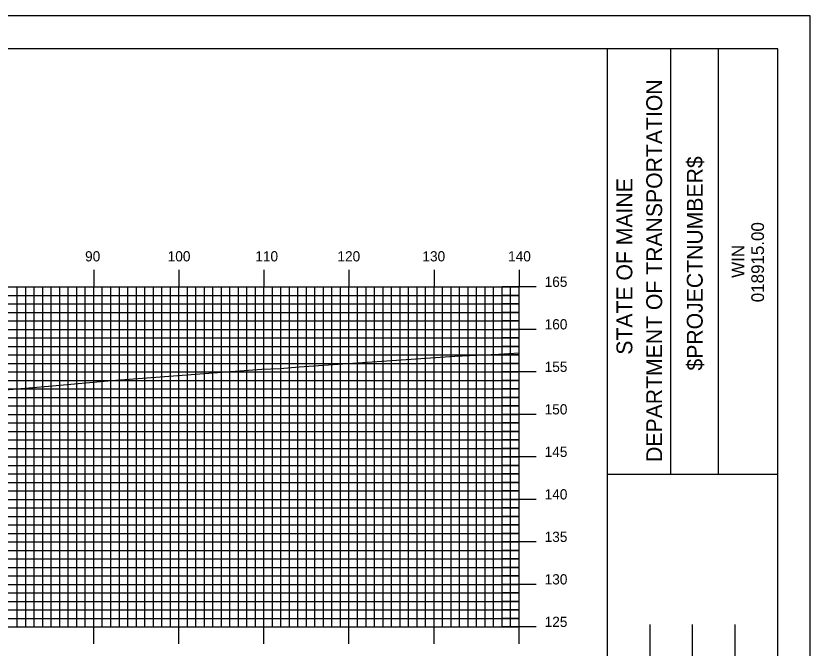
# Model space of a CAD drawing. Extents: x 1782647 to 1782990, y 442591 to 442811.
# Drawn here: x 1782893.8 to 1782987.2, y 442736.2 to 442810.5 of the extents above; entities that cross this region are included whole.
import ezdxf

# ---------------------------------------------------------------- set-up
doc = ezdxf.new("R2010")
doc.units = 0
for name, color, linetype in [('BORDER', 7, 'Continuous'), ('H_V ANNOTATION', 7, 'Continuous'), ('MAJOR', 7, 'Continuous'), ('MINOR', 7, 'Continuous'), ('PLOT BOUNDARY', 7, 'Continuous'), ('S_Roadway_Centerline', 7, 'Continuous')]:
    doc.layers.add(name, color=color, linetype=linetype)

msp = doc.modelspace()

# ---------------------------------------------------------------- linework, layer by layer
at = {"layer": 'BORDER'}
for p, q in [((1782963.347, 442596.665), (1782963.347, 442806.665)), ((1782970.804, 442756.659), (1782970.804, 442806.659)), ((1782976.394, 442756.659), (1782976.394, 442806.659)), ((1782963.349, 442756.653), (1782983.347, 442756.653)), ((1782963.349, 442756.653), (1782983.347, 442756.653)), ((1782968.347, 442721.671), (1782968.347, 442738.966)), ((1782968.347, 442721.671), (1782968.347, 442738.966)), ((1782973.347, 442721.671), (1782973.347, 442738.966)), ((1782973.347, 442721.671), (1782973.347, 442738.966)), ((1782978.347, 442721.671), (1782978.347, 442738.966)), ((1782978.347, 442721.671), (1782978.347, 442738.966))]:
    msp.add_line(p, q, dxfattribs=at)
msp.add_lwpolyline([(1782663.347, 442596.665), (1782983.347, 442596.665), (1782983.347, 442806.665), (1782663.347, 442806.665)], close=True, dxfattribs=at)
at = {"layer": 'MAJOR'}
for p, q in [((1782902.947, 442780.669), (1782902.947, 442778.665)), ((1782912.947, 442780.669), (1782912.947, 442778.665)), ((1782922.947, 442780.669), (1782922.947, 442778.665)), ((1782932.947, 442780.669), (1782932.947, 442778.665)), ((1782942.947, 442780.669), (1782942.947, 442778.665)), ((1782952.947, 442780.669), (1782952.947, 442778.665)), ((1782672.947, 442778.665), (1782952.947, 442778.665)), ((1782672.947, 442778.665), (1782952.947, 442778.665)), ((1782902.947, 442738.665), (1782902.947, 442778.665)), ((1782912.947, 442738.665), (1782912.947, 442778.665)), ((1782922.947, 442738.665), (1782922.947, 442778.665)), ((1782932.947, 442738.665), (1782932.947, 442778.665)), ((1782942.947, 442738.665), (1782942.947, 442778.665)), ((1782954.951, 442778.665), (1782950.943, 442778.665)), ((1782952.947, 442738.665), (1782952.947, 442778.665)), ((1782952.947, 442738.665), (1782952.947, 442778.665)), ((1782672.947, 442773.665), (1782952.947, 442773.665)), ((1782954.951, 442773.665), (1782950.943, 442773.665)), ((1782672.947, 442768.665), (1782952.947, 442768.665)), ((1782954.951, 442768.665), (1782950.943, 442768.665)), ((1782672.947, 442763.665), (1782952.947, 442763.665)), ((1782954.951, 442763.665), (1782950.943, 442763.665)), ((1782672.947, 442758.665), (1782952.947, 442758.665)), ((1782954.951, 442758.665), (1782950.943, 442758.665)), ((1782672.947, 442753.665), (1782952.947, 442753.665)), ((1782954.951, 442753.665), (1782950.943, 442753.665)), ((1782672.947, 442748.665), (1782952.947, 442748.665)), ((1782954.951, 442748.665), (1782950.943, 442748.665)), ((1782672.947, 442743.665), (1782952.947, 442743.665)), ((1782954.951, 442743.665), (1782950.943, 442743.665)), ((1782672.947, 442738.665), (1782952.947, 442738.665)), ((1782672.947, 442738.665), (1782952.947, 442738.665)), ((1782902.947, 442736.661), (1782902.947, 442738.665)), ((1782912.947, 442736.661), (1782912.947, 442738.665)), ((1782922.947, 442736.661), (1782922.947, 442738.665)), ((1782932.947, 442736.661), (1782932.947, 442738.665)), ((1782942.947, 442736.661), (1782942.947, 442738.665)), ((1782954.951, 442738.665), (1782950.943, 442738.665)), ((1782952.947, 442736.661), (1782952.947, 442738.665))]:
    msp.add_line(p, q, dxfattribs=at)
at = {"layer": 'MINOR'}
for p, q in [((1782893.947, 442738.665), (1782893.947, 442778.665)), ((1782894.947, 442738.665), (1782894.947, 442778.665)), ((1782895.947, 442738.665), (1782895.947, 442778.665)), ((1782896.947, 442738.665), (1782896.947, 442778.665)), ((1782897.947, 442738.665), (1782897.947, 442778.665)), ((1782898.947, 442738.665), (1782898.947, 442778.665)), ((1782899.947, 442738.665), (1782899.947, 442778.665)), ((1782900.947, 442738.665), (1782900.947, 442778.665)), ((1782901.947, 442738.665), (1782901.947, 442778.665)), ((1782903.947, 442738.665), (1782903.947, 442778.665)), ((1782904.947, 442738.665), (1782904.947, 442778.665)), ((1782905.947, 442738.665), (1782905.947, 442778.665)), ((1782906.947, 442738.665), (1782906.947, 442778.665)), ((1782907.947, 442738.665), (1782907.947, 442778.665)), ((1782908.947, 442738.665), (1782908.947, 442778.665)), ((1782909.947, 442738.665), (1782909.947, 442778.665)), ((1782910.947, 442738.665), (1782910.947, 442778.665)), ((1782911.947, 442738.665), (1782911.947, 442778.665)), ((1782913.947, 442738.665), (1782913.947, 442778.665)), ((1782914.947, 442738.665), (1782914.947, 442778.665)), ((1782915.947, 442738.665), (1782915.947, 442778.665)), ((1782916.947, 442738.665), (1782916.947, 442778.665)), ((1782917.947, 442738.665), (1782917.947, 442778.665)), ((1782918.947, 442738.665), (1782918.947, 442778.665)), ((1782919.947, 442738.665), (1782919.947, 442778.665)), ((1782920.947, 442738.665), (1782920.947, 442778.665)), ((1782921.947, 442738.665), (1782921.947, 442778.665)), ((1782923.947, 442738.665), (1782923.947, 442778.665)), ((1782924.947, 442738.665), (1782924.947, 442778.665)), ((1782925.947, 442738.665), (1782925.947, 442778.665)), ((1782926.947, 442738.665), (1782926.947, 442778.665)), ((1782927.947, 442738.665), (1782927.947, 442778.665)), ((1782928.947, 442738.665), (1782928.947, 442778.665)), ((1782929.947, 442738.665), (1782929.947, 442778.665)), ((1782930.947, 442738.665), (1782930.947, 442778.665)), ((1782931.947, 442738.665), (1782931.947, 442778.665)), ((1782933.947, 442738.665), (1782933.947, 442778.665)), ((1782934.947, 442738.665), (1782934.947, 442778.665)), ((1782935.947, 442738.665), (1782935.947, 442778.665)), ((1782936.947, 442738.665), (1782936.947, 442778.665)), ((1782937.947, 442738.665), (1782937.947, 442778.665)), ((1782938.947, 442738.665), (1782938.947, 442778.665)), ((1782939.947, 442738.665), (1782939.947, 442778.665)), ((1782940.947, 442738.665), (1782940.947, 442778.665)), ((1782941.947, 442738.665), (1782941.947, 442778.665)), ((1782943.947, 442738.665), (1782943.947, 442778.665)), ((1782944.947, 442738.665), (1782944.947, 442778.665)), ((1782945.947, 442738.665), (1782945.947, 442778.665)), ((1782946.947, 442738.665), (1782946.947, 442778.665)), ((1782947.947, 442738.665), (1782947.947, 442778.665)), ((1782948.947, 442738.665), (1782948.947, 442778.665)), ((1782949.947, 442738.665), (1782949.947, 442778.665)), ((1782950.947, 442738.665), (1782950.947, 442778.665)), ((1782951.947, 442738.665), (1782951.947, 442778.665)), ((1782672.947, 442777.665), (1782952.947, 442777.665)), ((1782952.947, 442777.665), (1782950.943, 442777.665)), ((1782672.947, 442776.665), (1782952.947, 442776.665)), ((1782952.947, 442776.665), (1782950.943, 442776.665)), ((1782672.947, 442775.665), (1782952.947, 442775.665)), ((1782952.947, 442775.665), (1782950.943, 442775.665)), ((1782672.947, 442774.665), (1782952.947, 442774.665)), ((1782952.947, 442774.665), (1782950.943, 442774.665)), ((1782672.947, 442772.665), (1782952.947, 442772.665)), ((1782952.947, 442772.665), (1782950.943, 442772.665)), ((1782672.947, 442771.665), (1782952.947, 442771.665)), ((1782952.947, 442771.665), (1782950.943, 442771.665)), ((1782672.947, 442770.665), (1782952.947, 442770.665)), ((1782952.947, 442770.665), (1782950.943, 442770.665)), ((1782672.947, 442769.665), (1782952.947, 442769.665)), ((1782952.947, 442769.665), (1782950.943, 442769.665)), ((1782672.947, 442767.665), (1782952.947, 442767.665)), ((1782952.947, 442767.665), (1782950.943, 442767.665)), ((1782672.947, 442766.665), (1782952.947, 442766.665)), ((1782952.947, 442766.665), (1782950.943, 442766.665)), ((1782672.947, 442765.665), (1782952.947, 442765.665)), ((1782952.947, 442765.665), (1782950.943, 442765.665)), ((1782672.947, 442764.665), (1782952.947, 442764.665)), ((1782952.947, 442764.665), (1782950.943, 442764.665)), ((1782672.947, 442762.665), (1782952.947, 442762.665)), ((1782952.947, 442762.665), (1782950.943, 442762.665)), ((1782672.947, 442761.665), (1782952.947, 442761.665)), ((1782952.947, 442761.665), (1782950.943, 442761.665)), ((1782672.947, 442760.665), (1782952.947, 442760.665)), ((1782952.947, 442760.665), (1782950.943, 442760.665)), ((1782672.947, 442759.665), (1782952.947, 442759.665)), ((1782952.947, 442759.665), (1782950.943, 442759.665)), ((1782672.947, 442757.665), (1782952.947, 442757.665)), ((1782952.947, 442757.665), (1782950.943, 442757.665)), ((1782672.947, 442756.665), (1782952.947, 442756.665)), ((1782952.947, 442756.665), (1782950.943, 442756.665)), ((1782672.947, 442755.665), (1782952.947, 442755.665)), ((1782952.947, 442755.665), (1782950.943, 442755.665)), ((1782672.947, 442754.665), (1782952.947, 442754.665)), ((1782952.947, 442754.665), (1782950.943, 442754.665)), ((1782672.947, 442752.665), (1782952.947, 442752.665)), ((1782952.947, 442752.665), (1782950.943, 442752.665)), ((1782672.947, 442751.665), (1782952.947, 442751.665)), ((1782952.947, 442751.665), (1782950.943, 442751.665)), ((1782672.947, 442750.665), (1782952.947, 442750.665)), ((1782952.947, 442750.665), (1782950.943, 442750.665)), ((1782672.947, 442749.665), (1782952.947, 442749.665)), ((1782952.947, 442749.665), (1782950.943, 442749.665)), ((1782672.947, 442747.665), (1782952.947, 442747.665)), ((1782952.947, 442747.665), (1782950.943, 442747.665)), ((1782672.947, 442746.665), (1782952.947, 442746.665)), ((1782952.947, 442746.665), (1782950.943, 442746.665)), ((1782672.947, 442745.665), (1782952.947, 442745.665)), ((1782952.947, 442745.665), (1782950.943, 442745.665)), ((1782672.947, 442744.665), (1782952.947, 442744.665)), ((1782952.947, 442744.665), (1782950.943, 442744.665)), ((1782672.947, 442742.665), (1782952.947, 442742.665)), ((1782952.947, 442742.665), (1782950.943, 442742.665)), ((1782672.947, 442741.665), (1782952.947, 442741.665)), ((1782952.947, 442741.665), (1782950.943, 442741.665)), ((1782672.947, 442740.665), (1782952.947, 442740.665)), ((1782952.947, 442740.665), (1782950.943, 442740.665)), ((1782672.947, 442739.665), (1782952.947, 442739.665)), ((1782952.947, 442739.665), (1782950.943, 442739.665))]:
    msp.add_line(p, q, dxfattribs=at)
at = {"layer": 'PLOT BOUNDARY'}
msp.add_lwpolyline([(1782647.16, 442590.547), (1782987.16, 442590.547), (1782987.16, 442810.547), (1782647.16, 442810.547)], close=True, dxfattribs=at)
at = {"layer": 'S_Roadway_Centerline'}
msp.add_lwpolyline([(1782754.648, 442754.657), (1782769.593, 442756.227), (1782773.527, 442756.474), (1782777.916, 442756.82), (1782791.93, 442758.044), (1782802.937, 442758.841), (1782808.832, 442759.308), (1782813.97, 442759.687), (1782819.988, 442760.06), (1782826.852, 442760.544), (1782831.867, 442760.789), (1782836.302, 442761.011), (1782850.244, 442761.818), (1782859.12, 442762.66), (1782866.161, 442763.643), (1782881.365, 442765.601), (1782898.087, 442767.02), (1782905.017, 442767.662), (1782922.687, 442768.978), (1782924.841, 442769.069), (1782927.077, 442769.258), (1782945.373, 442770.509), (1782950.533, 442770.74), (1782952.947, 442770.911)], dxfattribs=at)

# ---------------------------------------------------------------- texts
at = {"layer": 'BORDER'}
for s, height, p in [('DEPARTMENT OF TRANSPORTATION', 1.86351, (1782969.761, 442758.077)), ('$PROJECTNUMBER$', 1.86351, (1782974.531, 442768.823)), ('$PROJECTNUMBER$', 1.86351, (1782974.531, 442768.823)), ('STATE OF MAINE', 1.86351, (1782966.258, 442770.689)), ('018915.00', 1.4905, (1782981.738, 442776.861)), ('WIN', 1.4905, (1782979.421, 442779.725)), ('WIN', 1.4905, (1782979.421, 442779.725))]:
    msp.add_text(s, height=height, rotation=90, dxfattribs=at).set_placement(p)
at = {"layer": 'H_V ANNOTATION'}
for s, p in [('90', (1782901.919, 442781.665)), ('100', (1782911.63, 442781.665)), ('110', (1782921.93, 442781.665)), ('120', (1782931.588, 442781.665)), ('130', (1782941.577, 442781.665)), ('140', (1782951.652, 442781.665)), ('165', (1782955.947, 442778.665)), ('160', (1782955.947, 442773.665)), ('155', (1782955.947, 442768.665)), ('150', (1782955.947, 442763.665)), ('145', (1782955.947, 442758.665)), ('140', (1782955.947, 442753.665)), ('135', (1782955.947, 442748.665)), ('130', (1782955.947, 442743.665)), ('125', (1782955.947, 442738.665))]:
    msp.add_text(s, height=1.2, dxfattribs=at).set_placement(p)

doc.saveas('drawing.dxf')
